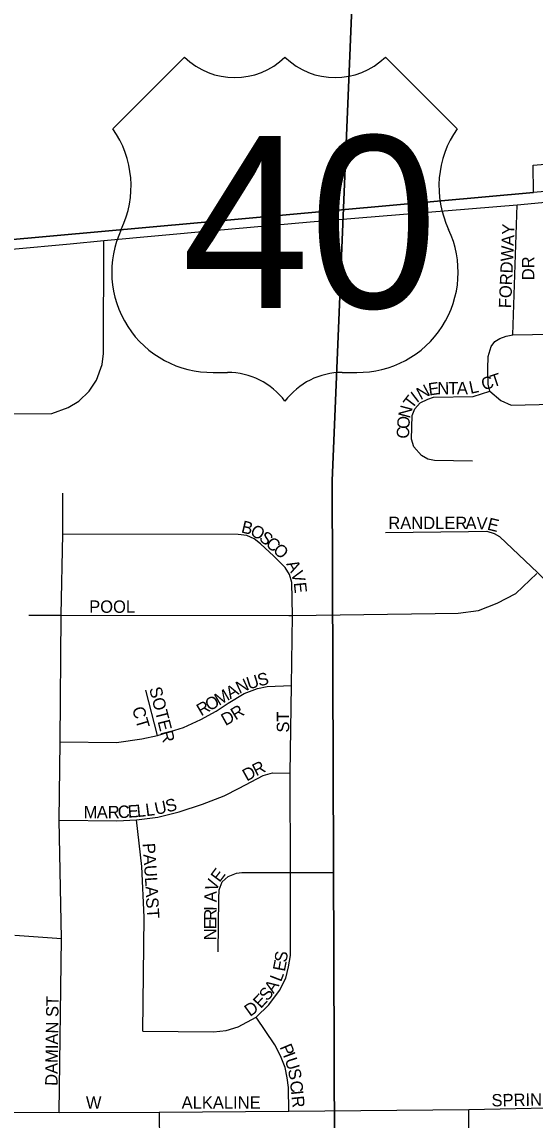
# Model space of a CAD drawing. Extents: x 8.5 to 81.5, y -1.2 to 22.4.
# Drawn here: x 50.981 to 51.374, y 18.88 to 19.722 of the extents above; entities that cross this region are included whole.
import ezdxf

# ---------------------------------------------------------------- set-up
doc = ezdxf.new("R2010")
doc.units = 0
for name, color, linetype in [('GM_X_City_Street', 7, 'Continuous'), ('GM_X_City_Street_Text', 7, 'Continuous'), ('GM_X_Corporation', 7, 'Continuous'), ('GM_X_Section', 7, 'Continuous'), ('GM_X_US_Location', 7, 'Continuous'), ('GM_X_US_Route', 7, 'Continuous'), ('GM_X_US_Shield', 7, 'Continuous')]:
    doc.layers.add(name, color=color, linetype=linetype)

msp = doc.modelspace()

# ---------------------------------------------------------------- linework, layer by layer
at = {"layer": 'GM_X_City_Street'}
for points in [[(51.33929, 19.4389), (51.33795, 19.4441), (51.33766, 19.45604), (51.33795, 19.46529), (51.34026, 19.473), (51.34315, 19.47685), (51.34681, 19.47916), (51.35181, 19.48099), (51.35682, 19.48211), (51.3602, 19.5816)], [(50.91243, 19.14318), (50.91679, 19.15346), (50.91914, 19.31773), (50.91958, 19.36302), (50.92048, 19.3713), (50.92367, 19.38209), (50.92886, 19.39159), (50.93373, 19.39869), (50.93988, 19.40529), (50.94726, 19.41122), (50.95447, 19.41513), (50.96286, 19.41887), (50.97415, 19.42139), (51.00373, 19.42178), (51.0162, 19.4262), (51.02436, 19.43107), (51.03236, 19.43884), (51.03795, 19.44728), (51.04237, 19.4593), (51.04326, 19.46774), (51.0434, 19.55417)], [(51.35682, 19.48211), (51.53665, 19.48503)], [(51.32597, 19.38525), (51.29694, 19.38572), (51.29175, 19.38666), (51.28679, 19.38949), (51.28113, 19.3961), (51.27924, 19.402), (51.27971, 19.42017), (51.28184, 19.42536), (51.28585, 19.42985), (51.29175, 19.43268), (51.296, 19.43433), (51.32644, 19.4348), (51.33929, 19.4389)], [(51.33929, 19.4389), (51.34758, 19.43158), (51.35567, 19.42811), (51.53837, 19.43236)], [(51.00926, 18.88596), (51.01104, 19.01941), (51.00926, 19.10992), (51.01006, 19.17), (51.01096, 19.26706), (51.01096, 19.2673), (51.0121, 19.3292), (51.01199, 19.36061)], [(51.25939, 19.33056), (51.32288, 19.3313), (51.33704, 19.33142), (51.34253, 19.32971), (51.34656, 19.32739), (51.37599, 19.29965), (51.39553, 19.28063), (51.40602, 19.26915), (51.40822, 19.2628), (51.40883, 19.25205), (51.40683, 18.88998)], [(51.18797, 19.26692), (51.18767, 19.29218), (51.18572, 19.29837), (51.18253, 19.30379), (51.17387, 19.31246), (51.16343, 19.32171), (51.15874, 19.32553), (51.15301, 19.32818), (51.14654, 19.32905), (51.0121, 19.3292)], [(51.18519, 19.26692), (51.18797, 19.26692), (51.29737, 19.26835), (51.31509, 19.26864), (51.33063, 19.27067), (51.34486, 19.27634), (51.35909, 19.28374), (51.37528, 19.29898)], [(50.98601, 19.26704), (51.00593, 19.26706)], [(51.00593, 19.26706), (51.01096, 19.26706), (51.18519, 19.26692)], [(51.07339, 18.94829), (51.12744, 18.94784), (51.13714, 18.94873), (51.1464, 18.95152), (51.1602, 18.95901), (51.17005, 18.96855), (51.17798, 18.97958), (51.18283, 18.98883), (51.18496, 18.9977), (51.18665, 19.00631), (51.18665, 19.06996), (51.18621, 19.14616), (51.18723, 19.21315), (51.18797, 19.26692)], [(51.01006, 19.17), (51.05317, 19.16959), (51.07263, 19.17225), (51.08458, 19.1749), (51.10447, 19.18106), (51.11787, 19.18716), (51.12948, 19.1937), (51.13877, 19.19967), (51.15105, 19.20709), (51.16122, 19.21085), (51.16875, 19.2125), (51.18723, 19.21315)], [(51.08458, 19.1749), (51.07575, 19.20968)], [(51.00926, 19.10992), (51.05355, 19.10946), (51.06859, 19.11031), (51.08479, 19.11246), (51.10129, 19.11634), (51.11917, 19.12234), (51.13564, 19.12876), (51.14731, 19.13457), (51.16553, 19.14429), (51.17271, 19.14623), (51.18621, 19.14616)], [(51.07339, 18.94829), (51.07442, 19.03565), (51.07266, 19.07445), (51.06859, 19.11031)], [(51.131, 19.00901), (51.13153, 19.04964), (51.1318, 19.05659), (51.1342, 19.06274), (51.13875, 19.06675), (51.14517, 19.06942), (51.14917, 19.06996), (51.18665, 19.06996), (51.21882, 19.06996)], [(50.97543, 19.02182), (51.01104, 19.01941)], [(51.18527, 18.88702), (51.18509, 18.90514), (51.184, 18.91263), (51.18234, 18.92046), (51.17892, 18.92939), (51.17451, 18.93777), (51.1602, 18.95901)], [(50.97208, 18.88635), (51.00926, 18.88596), (51.08581, 18.88617), (51.18527, 18.88702), (51.32318, 18.88832), (51.40683, 18.88998), (51.46707, 18.89134), (51.71744, 18.89515)], [(51.08581, 18.88617), (51.08646, 18.83928), (51.09292, 18.83018)], [(51.30578, 18.35094), (51.30585, 18.41448), (51.30562, 18.44672), (51.3059, 18.60754), (51.30576, 18.66515), (51.30588, 18.73928), (51.30624, 18.75241), (51.30555, 18.78466), (51.30709, 18.79379), (51.31319, 18.80717), (51.31816, 18.81444), (51.32344, 18.8291), (51.32318, 18.88832)]]:
    msp.add_lwpolyline(points, dxfattribs=at)
at = {"layer": 'GM_X_Corporation'}
for points in [[(52.25936, 21.01123), (52.2567, 20.86959), (52.25158, 20.86932), (52.23976, 20.8687), (52.27094, 19.9771), (52.217, 19.97523), (52.21768, 19.95576), (52.27298, 19.92635), (52.27419, 19.89183), (52.23539, 19.89048), (52.23716, 19.83987), (52.15793, 19.84059), (52.15789, 19.7505), (52.03952, 19.75051), (52.03953, 19.65129), (51.91664, 19.6402), (51.55407, 19.60748), (51.42733, 19.59604), (51.3727, 19.59111), (49.93264, 19.46099)], [(49.93264, 19.46099), (51.3727, 19.59111), (51.37231, 19.61199), (51.42697, 19.61665), (51.42733, 19.59604), (51.55407, 19.60748), (51.52016, 19.82136), (51.54761, 19.84881), (51.9245, 19.84882), (51.95067, 19.80163), (51.94688, 19.69284), (51.91847, 19.69284), (51.91664, 19.6402), (52.03953, 19.65129), (52.03952, 19.75051), (52.15789, 19.7505)]]:
    msp.add_lwpolyline(points, dxfattribs=at)
at = {"layer": 'GM_X_Section'}
for points in [[(51.23908, 19.86864), (51.2184, 19.37023), (51.22018, 18.85778), (50.25093, 18.85429), (50.25474, 19.34203), (50.28125, 19.86873)], [(52.28397, 19.8673), (52.22193, 19.20227), (52.2136, 18.89831), (51.6895, 18.86113), (51.22018, 18.85778), (51.2184, 19.37023), (51.23908, 19.86864)]]:
    msp.add_lwpolyline(points, close=True, dxfattribs=at)
at = {"layer": 'GM_X_US_Route'}
for points in [[(51.1273, 19.56184), (51.20147, 19.56862), (51.3602, 19.5816), (51.53494, 19.59813), (51.63523, 19.60658), (51.74541, 19.61584), (51.80651, 19.62072), (51.87925, 19.62701), (51.96146, 19.63302), (52.05486, 19.64115), (52.05585, 19.64124)], [(51.01767, 19.55182), (51.0434, 19.55417), (51.1273, 19.56184)], [(50.92798, 19.54362), (51.01767, 19.55182)]]:
    msp.add_lwpolyline(points, dxfattribs=at)
at = {"layer": 'GM_X_US_Shield'}
for p, q in [((51.10538, 19.69487), (51.05045, 19.63994)), ((51.31412, 19.63994), (51.25919, 19.69487)), ((51.12735, 19.45317), (51.13834, 19.45317)), ((51.22623, 19.45317), (51.23722, 19.45317))]:
    msp.add_line(p, q, dxfattribs=at)
for centre, radius, start, end in [((51.14383, 19.7341), 0.05493, 225.573, 314.427), ((51.22074, 19.7341), 0.05493, 225.573, 314.427), ((50.98745, 19.59582), 0.0769, 334.54712, 35.00093), ((51.37712, 19.59582), 0.0769, 144.99907, 205.45288), ((51.1265, 19.53007), 0.0769, 154.83192, 270.63826), ((51.23807, 19.53007), 0.0769, 269.36174, 25.16808), ((51.13834, 19.39824), 0.05493, 36.8699, 90), ((51.22623, 19.39824), 0.05493, 90, 143.1301)]:
    msp.add_arc(centre, radius, start, end, dxfattribs=at)

# ---------------------------------------------------------------- texts
at = {"layer": 'GM_X_City_Street_Text'}
for s, rotation, p in [('FORDWAY', 87.5473, (51.35551, 19.50224)), ('DR', 90, (51.37329, 19.52383)), ('C', 18.40423, (51.33448, 19.43922)), ('T', 18.43358, (51.3416, 19.44159)), ('N', 28.05063, (51.28622, 19.43183)), ('E', 7.6741, (51.29273, 19.43548)), ('N', 0.80878, (51.29904, 19.43635)), ('T', 0.21858, (51.30735, 19.43646)), ('A', 0.2186, (51.31401, 19.43649)), ('L', 11.91007, (51.32444, 19.43674)), ('T', 52.51803, (51.27966, 19.4247)), ('I', 37.34203, (51.28325, 19.42952)), ('N', 75.05731, (51.27795, 19.41752)), ('O', 86.89532, (51.27757, 19.40971)), ('C', 86.91445, (51.27717, 19.40222)), ('B', 346.21707, (51.14823, 19.33063)), ('RANDLER', 0.00001, (51.26145, 19.33311)), ('A', 359.69396, (51.32061, 19.33311)), ('V', 357.70415, (51.32885, 19.33307)), ('E', 346.26196, (51.33668, 19.33281)), ('O', 330.37439, (51.15487, 19.32909)), ('S', 319.8936, (51.16174, 19.32524)), ('C', 318.64275, (51.1668, 19.32098)), ('O', 318.61876, (51.17243, 19.31602)), ('A', 298.03135, (51.18299, 19.3064)), ('V', 286.32665, (51.18671, 19.29952)), ('E', 276.132, (51.18897, 19.29196)), ('POOL', 0.00001, (51.03229, 19.26895)), ('S', 13.59883, (51.16241, 19.21247)), ('A', 30.24224, (51.14037, 19.20255)), ('N', 25.00105, (51.14737, 19.20664)), ('U', 17.30839, (51.15461, 19.21004)), ('SOTER', 284.35156, (51.07818, 19.21094)), ('O', 30.24224, (51.12453, 19.19331)), ('M', 30.24095, (51.13173, 19.19751)), ('CT', 286.38258, (51.06504, 19.19557)), ('R', 30.23895, (51.11805, 19.18954)), ('R', 31.88172, (51.1444, 19.18639)), ('D', 28.99941, (51.13667, 19.18209)), ('ST', 90, (51.1855, 19.17716)), ('R', 26.67367, (51.16022, 19.14356)), ('D', 29.30298, (51.15305, 19.13954)), ('M', 0.01821, (51.02812, 19.11145)), ('A', 0.02626, (51.03812, 19.11145)), ('R', 0.59963, (51.04656, 19.11145)), ('C', 2.701, (51.05444, 19.11155)), ('E', 3.7052, (51.06211, 19.11191)), ('L', 5.58276, (51.06911, 19.11237)), ('L', 7.19765, (51.07603, 19.11305)), ('U', 11.8852, (51.08348, 19.11402)), ('S', 14.76035, (51.09214, 19.11586)), ('PAULA', 273.73368, (51.07324, 19.0922)), ('E', 52.88961, (51.13214, 19.06187)), ('V', 70.94304, (51.12979, 19.05468)), ('A', 89.60651, (51.12987, 19.04715)), ('ST', 273.57465, (51.07574, 19.05061)), ('R', 89.5871, (51.12978, 19.03298)), ('I', 89.6085, (51.12983, 19.04048)), ('E', 89.60583, (51.12973, 19.02631)), ('N', 89.60651, (51.12967, 19.01798)), ('E', 79.20136, (51.18217, 18.99365)), ('S', 81.94894, (51.1835, 19.00069)), ('A', 56.10619, (51.17353, 18.97669)), ('L', 68.75361, (51.17923, 18.98562)), ('S', 51.74332, (51.16894, 18.97081)), ('DAMIAN ST', 89.25634, (51.00801, 18.90635)), ('D', 35.62405, (51.15549, 18.95911)), ('E', 46.6443, (51.16376, 18.96527)), ('P', 292.62828, (51.17809, 18.93622)), ('I', 290.63277, (51.18062, 18.93015)), ('U', 287.49486, (51.18204, 18.92638)), ('S', 281.15995, (51.18448, 18.9187)), ('C', 276.27851, (51.18602, 18.90988)), ('I', 275.91064, (51.18684, 18.90245)), ('W', 0.00001, (51.02979, 18.88894)), ('ALKALINE', 0.00001, (51.10312, 18.88895)), ('R', 275.89992, (51.18727, 18.8983)), ('SPRINGS', 1.00455, (51.34059, 18.89061))]:
    msp.add_text(s, height=0.00947, rotation=rotation, dxfattribs=at).set_placement(p)
at = {"layer": 'GM_X_US_Location'}
for s in ['/', '0']:
    msp.add_text(s, height=0.000189, dxfattribs=at).set_placement((51.18222, 19.56749))
msp.add_text('40', height=0.000189, rotation=0.00001, dxfattribs=at).set_placement((51.14312, 19.52828))
at = {"layer": 'GM_X_US_Shield'}
msp.add_text('40', height=0.131836, dxfattribs=at).set_placement((51.10309, 19.50261))

doc.saveas('drawing.dxf')
